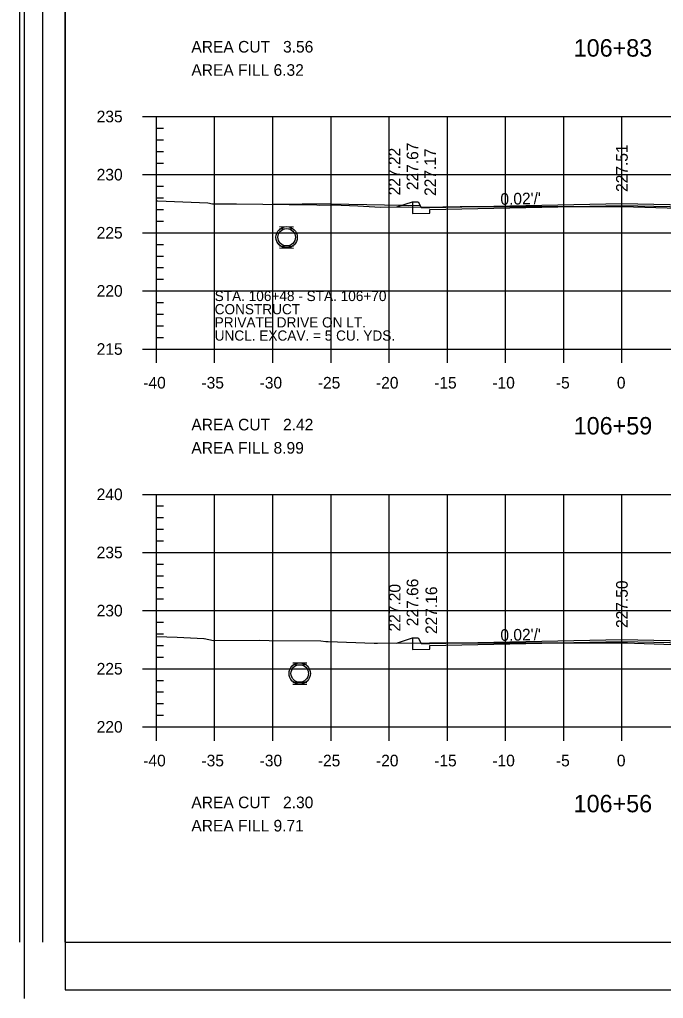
# Model space of a CAD drawing. Extents: x 1367903 to 1373764, y 376865 to 382130.
# Drawn here: x 1371403 to 1371513.6, y 377279.1 to 377447.5 of the extents above; entities that cross this region are included whole.
import ezdxf

# ---------------------------------------------------------------- set-up
doc = ezdxf.new("R2010")
doc.units = 0
for name, color, linetype in [('R_Axis', 7, 'Continuous'), ('R_Axis Annot', 7, 'Continuous'), ('R_Border', 7, 'Continuous'), ('R_Border PE', 7, 'Continuous'), ('R_Draft', 7, 'Continuous'), ('R_Drive', 7, 'Continuous'), ('R_Exist Surface', 7, 'Continuous'), ('R_Fin Surface', 7, 'Continuous'), ('R_Fin Surface Annot', 7, 'Continuous'), ('R_Grid', 7, 'Continuous'), ('R_Water', 7, 'Continuous')]:
    doc.layers.add(name, color=color, linetype=linetype)

msp = doc.modelspace()

# ---------------------------------------------------------------- linework, layer by layer
for points in [[(1371470.51, 377416.17), (1371470.51, 377415.5), (1371470.51, 377415.5), (1371470.51, 377414.14), (1371473.51, 377414.2), (1371473.51, 377414.87), (1371506.51, 377415.53), (1371539.51, 377414.87), (1371539.51, 377414.2), (1371542.51, 377414.14), (1371542.51, 377415.58), (1371556.51, 377415.86), (1371556.51, 377416.45)], [(1371470.51, 377341.15), (1371470.51, 377340.48), (1371470.51, 377340.48), (1371470.51, 377339.12), (1371473.51, 377339.18), (1371473.51, 377339.84), (1371506.51, 377340.5), (1371539.51, 377339.84), (1371539.51, 377339.18), (1371542.51, 377339.12), (1371542.51, 377340.56), (1371556.51, 377340.84), (1371556.51, 377341.43)]]:
    msp.add_lwpolyline(points)
at = {"layer": 'R_Axis'}
for p, q in [((1371424.11, 377430.84), (1371428.91, 377430.84)), ((1371426.51, 377390.84), (1371426.51, 377430.84)), ((1371426.51, 377428.84), (1371427.71, 377428.84)), ((1371426.51, 377426.84), (1371427.71, 377426.84)), ((1371426.51, 377424.84), (1371427.71, 377424.84)), ((1371426.51, 377422.84), (1371427.71, 377422.84)), ((1371424.11, 377420.84), (1371428.91, 377420.84)), ((1371426.51, 377418.84), (1371427.71, 377418.84)), ((1371426.51, 377416.84), (1371427.71, 377416.84)), ((1371426.51, 377414.84), (1371427.71, 377414.84)), ((1371426.51, 377412.84), (1371427.71, 377412.84)), ((1371424.11, 377410.84), (1371428.91, 377410.84)), ((1371426.51, 377408.84), (1371427.71, 377408.84)), ((1371426.51, 377406.84), (1371427.71, 377406.84)), ((1371426.51, 377404.84), (1371427.71, 377404.84)), ((1371426.51, 377402.84), (1371427.71, 377402.84)), ((1371424.11, 377400.84), (1371428.91, 377400.84)), ((1371426.51, 377398.84), (1371427.71, 377398.84)), ((1371426.51, 377396.84), (1371427.71, 377396.84)), ((1371426.51, 377394.84), (1371427.71, 377394.84)), ((1371426.51, 377388.44), (1371426.51, 377393.24)), ((1371426.51, 377392.84), (1371427.71, 377392.84)), ((1371436.51, 377388.44), (1371436.51, 377393.24)), ((1371446.51, 377388.44), (1371446.51, 377393.24)), ((1371456.51, 377388.44), (1371456.51, 377393.24)), ((1371466.51, 377388.44), (1371466.51, 377393.24)), ((1371476.51, 377388.44), (1371476.51, 377393.24)), ((1371486.51, 377388.44), (1371486.51, 377393.24)), ((1371496.51, 377388.44), (1371496.51, 377393.24)), ((1371506.51, 377388.44), (1371506.51, 377393.24)), ((1371424.11, 377390.84), (1371428.91, 377390.84)), ((1371426.51, 377390.84), (1371586.51, 377390.84)), ((1371424.11, 377365.84), (1371428.91, 377365.84)), ((1371426.51, 377325.84), (1371426.51, 377365.84)), ((1371426.51, 377363.84), (1371427.71, 377363.84)), ((1371426.51, 377361.84), (1371427.71, 377361.84)), ((1371426.51, 377359.84), (1371427.71, 377359.84)), ((1371426.51, 377357.84), (1371427.71, 377357.84)), ((1371424.11, 377355.84), (1371428.91, 377355.84)), ((1371426.51, 377353.84), (1371427.71, 377353.84)), ((1371426.51, 377351.84), (1371427.71, 377351.84)), ((1371426.51, 377349.84), (1371427.71, 377349.84)), ((1371426.51, 377347.84), (1371427.71, 377347.84)), ((1371424.11, 377345.84), (1371428.91, 377345.84)), ((1371426.51, 377343.84), (1371427.71, 377343.84)), ((1371426.51, 377341.84), (1371427.71, 377341.84)), ((1371426.51, 377339.84), (1371427.71, 377339.84)), ((1371426.51, 377337.84), (1371427.71, 377337.84)), ((1371424.11, 377335.84), (1371428.91, 377335.84)), ((1371426.51, 377333.84), (1371427.71, 377333.84)), ((1371426.51, 377331.84), (1371427.71, 377331.84)), ((1371426.51, 377329.84), (1371427.71, 377329.84)), ((1371426.51, 377323.44), (1371426.51, 377328.24)), ((1371436.51, 377323.44), (1371436.51, 377328.24)), ((1371446.51, 377323.44), (1371446.51, 377328.24)), ((1371456.51, 377323.44), (1371456.51, 377328.24)), ((1371466.51, 377323.44), (1371466.51, 377328.24)), ((1371476.51, 377323.44), (1371476.51, 377328.24)), ((1371486.51, 377323.44), (1371486.51, 377328.24)), ((1371496.51, 377323.44), (1371496.51, 377328.24)), ((1371506.51, 377323.44), (1371506.51, 377328.24)), ((1371426.51, 377327.84), (1371427.71, 377327.84)), ((1371424.11, 377325.84), (1371428.91, 377325.84)), ((1371426.51, 377325.84), (1371586.51, 377325.84))]:
    msp.add_line(p, q, dxfattribs=at)
at = {"layer": 'R_Border'}
for p, q in [((1371403.79, 377620.35), (1371403.79, 377279.12)), ((1371410.82, 377611.47), (1371410.82, 377280.59)), ((1371410.82, 377280.59), (1371615.14, 377280.59))]:
    msp.add_line(p, q, dxfattribs=at)
at = {"layer": 'R_Border PE'}
for p, q in [((1371402.98, 377610.76), (1371402.98, 377288.8)), ((1371406.9, 377610.76), (1371406.9, 377288.8)), ((1371410.82, 377288.8), (1371410.82, 377603.25)), ((1371410.82, 377288.8), (1371615.14, 377288.8))]:
    msp.add_line(p, q, dxfattribs=at)
at = {"layer": 'R_Drive'}
for q in [(1371446.51, 377415.73), (1371471.84, 377415.51)]:
    msp.add_line((1371456.51, 377415.82), q, dxfattribs=at)
at = {"layer": 'R_Exist Surface'}
for points in [[(1371426.51, 377416.35), (1371426.76, 377416.34), (1371435.31, 377415.98), (1371436.13, 377415.79), (1371440.26, 377415.82), (1371449.34, 377415.69), (1371454.06, 377415.64), (1371454.52, 377415.6), (1371456.84, 377415.63), (1371461.14, 377415.47), (1371465, 377415.26), (1371469.81, 377415.29), (1371473.52, 377415.27), (1371474.46, 377415.26), (1371475.08, 377415.26), (1371475.72, 377415.28), (1371478.73, 377415.35), (1371503.55, 377415.38), (1371506.64, 377415.36), (1371516.16, 377415.09)], [(1371426.51, 377341.38), (1371430.09, 377341.24), (1371434.66, 377341.05), (1371434.73, 377341.05), (1371436.3, 377340.69), (1371444.24, 377340.74), (1371445.88, 377340.72), (1371454.77, 377340.61), (1371455.64, 377340.54), (1371456.04, 377340.55), (1371463.95, 377340.24), (1371464.52, 377340.21), (1371473.41, 377340.28), (1371473.99, 377340.28), (1371475.53, 377340.27), (1371475.68, 377340.27), (1371475.84, 377340.27), (1371476.57, 377340.29), (1371506.52, 377340.32), (1371506.76, 377340.32), (1371507.49, 377340.3), (1371508.7, 377340.26), (1371525.47, 377339.64)]]:
    msp.add_lwpolyline(points, dxfattribs=at)
at = {"layer": 'R_Fin Surface'}
for points in [[(1371467.84, 377415.28), (1371470.51, 377416.17), (1371471.51, 377416.17), (1371472.01, 377415.17), (1371473.51, 377415.2), (1371495.51, 377415.64), (1371506.51, 377415.86), (1371517.51, 377415.64), (1371539.51, 377415.2), (1371541.01, 377415.17), (1371541.51, 377416.17), (1371542.51, 377416.17), (1371546.51, 377416.25), (1371556.51, 377416.45), (1371562.02, 377414.61)], [(1371467.79, 377340.24), (1371470.51, 377341.15), (1371471.51, 377341.15), (1371472.01, 377340.15), (1371473.51, 377340.18), (1371495.51, 377340.62), (1371506.51, 377340.84), (1371517.51, 377340.62), (1371539.51, 377340.18), (1371541.01, 377340.15), (1371541.51, 377341.15), (1371542.51, 377341.15), (1371546.51, 377341.23), (1371556.51, 377341.43), (1371561.98, 377339.6)]]:
    msp.add_lwpolyline(points, dxfattribs=at)
at = {"layer": 'R_Grid'}
for p, q in [((1371426.51, 377430.84), (1371586.51, 377430.84)), ((1371426.51, 377390.84), (1371426.51, 377430.84)), ((1371436.51, 377390.84), (1371436.51, 377430.84)), ((1371446.51, 377390.84), (1371446.51, 377430.84)), ((1371456.51, 377390.84), (1371456.51, 377430.84)), ((1371466.51, 377390.84), (1371466.51, 377430.84)), ((1371476.51, 377390.84), (1371476.51, 377430.84)), ((1371486.51, 377390.84), (1371486.51, 377430.84)), ((1371496.51, 377390.84), (1371496.51, 377430.84)), ((1371506.51, 377390.84), (1371506.51, 377430.84)), ((1371426.51, 377420.84), (1371586.51, 377420.84)), ((1371426.51, 377410.84), (1371586.51, 377410.84)), ((1371426.51, 377400.84), (1371586.51, 377400.84)), ((1371426.51, 377390.84), (1371586.51, 377390.84)), ((1371426.51, 377365.84), (1371586.51, 377365.84)), ((1371426.51, 377325.84), (1371426.51, 377365.84)), ((1371436.51, 377325.84), (1371436.51, 377365.84)), ((1371446.51, 377325.84), (1371446.51, 377365.84)), ((1371456.51, 377325.84), (1371456.51, 377365.84)), ((1371466.51, 377325.84), (1371466.51, 377365.84)), ((1371476.51, 377325.84), (1371476.51, 377365.84)), ((1371486.51, 377325.84), (1371486.51, 377365.84)), ((1371496.51, 377325.84), (1371496.51, 377365.84)), ((1371506.51, 377325.84), (1371506.51, 377365.84)), ((1371426.51, 377355.84), (1371586.51, 377355.84)), ((1371426.51, 377345.84), (1371586.51, 377345.84)), ((1371426.51, 377335.84), (1371586.51, 377335.84)), ((1371426.51, 377325.84), (1371586.51, 377325.84))]:
    msp.add_line(p, q, dxfattribs=at)
at = {"layer": 'R_Water'}
for p, q in [((1371447.68, 377411.93), (1371450.08, 377411.88)), ((1371447.68, 377411.59), (1371450.08, 377411.54)), ((1371447.68, 377408.59), (1371450.08, 377408.54)), ((1371447.68, 377408.26), (1371450.08, 377408.21)), ((1371449.92, 377336.88), (1371452.33, 377336.83)), ((1371449.92, 377336.55), (1371452.33, 377336.5)), ((1371449.92, 377333.55), (1371452.33, 377333.5)), ((1371449.92, 377333.21), (1371452.33, 377333.16))]:
    msp.add_line(p, q, dxfattribs=at)
for centre, radius in [((1371448.88, 377410.07), 1.83), ((1371448.88, 377410.07), 1.5), ((1371451.13, 377335.02), 1.83), ((1371451.13, 377335.02), 1.5)]:
    msp.add_circle(centre, radius, dxfattribs=at)

# ---------------------------------------------------------------- texts
at = {"layer": 'R_Axis Annot'}
for s, height, p in [('AREA CUT   3.56', 2, (1371432.51, 377441.84)), ('106+83', 3, (1371498.22, 377441.14)), ('AREA FILL 6.32', 2, (1371432.51, 377437.84)), ('235', 2, (1371416.23, 377429.84)), ('230', 2, (1371416.23, 377419.84)), ('225', 2, (1371416.23, 377409.84)), ('220', 2, (1371416.23, 377399.84)), ('215', 2, (1371416.23, 377389.84)), ('-40', 2, (1371424.24, 377384.04)), ('-35', 2, (1371434.24, 377384.04)), ('-30', 2, (1371444.24, 377384.04)), ('-25', 2, (1371454.24, 377384.04)), ('-20', 2, (1371464.24, 377384.04)), ('-15', 2, (1371474.24, 377384.04)), ('-10', 2, (1371484.24, 377384.04)), ('-5', 2, (1371495.17, 377384.04)), ('0', 2, (1371505.64, 377384.04)), ('AREA CUT   2.42', 2, (1371432.51, 377376.84)), ('106+59', 3, (1371498.22, 377376.14)), ('AREA FILL 8.99', 2, (1371432.51, 377372.84)), ('240', 2, (1371416.23, 377364.84)), ('235', 2, (1371416.23, 377354.84)), ('230', 2, (1371416.23, 377344.84)), ('225', 2, (1371416.23, 377334.84)), ('220', 2, (1371416.23, 377324.84)), ('-40', 2, (1371424.24, 377319.04)), ('-35', 2, (1371434.24, 377319.04)), ('-30', 2, (1371444.24, 377319.04)), ('-25', 2, (1371454.24, 377319.04)), ('-20', 2, (1371464.24, 377319.04)), ('-15', 2, (1371474.24, 377319.04)), ('-10', 2, (1371484.24, 377319.04)), ('-5', 2, (1371495.17, 377319.04)), ('0', 2, (1371505.64, 377319.04)), ('AREA CUT   2.30', 2, (1371432.51, 377311.84)), ('106+56', 3, (1371498.21, 377311.14)), ('AREA FILL 9.71', 2, (1371432.51, 377307.84))]:
    msp.add_text(s, height=height, dxfattribs=at).set_placement(p)
at = {"layer": 'R_Draft'}
for s, p in [('STA. 106+48 - STA. 106+70', (1371436.51, 377399.09)), ('CONSTRUCT', (1371436.51, 377396.82)), ('PRIVATE DRIVE ON LT.', (1371436.51, 377394.55)), ('UNCL. EXCAV. = 5 CU. YDS.', (1371436.51, 377392.28))]:
    msp.add_text(s, height=1.75, dxfattribs=at).set_placement(p)
at = {"layer": 'R_Fin Surface Annot'}
for s, rotation, p in [('227.67', 90, (1371471.51, 377418.17)), ('227.51', 90, (1371507.51, 377417.86)), ('227.22', 90, (1371468.4, 377417.28)), ('227.17', 90, (1371474.57, 377417.17)), ("0.02'/'", 1.1456, (1371485.64, 377415.64)), ('227.20', 90, (1371468.45, 377342.24)), ('227.66', 90, (1371471.51, 377343.15)), ('227.50', 90, (1371507.51, 377342.84)), ('227.16', 90, (1371474.75, 377341.81)), ("0.02'/'", 1.1457, (1371485.64, 377340.62))]:
    msp.add_text(s, height=2, rotation=rotation, dxfattribs=at).set_placement(p)

doc.saveas('drawing.dxf')
